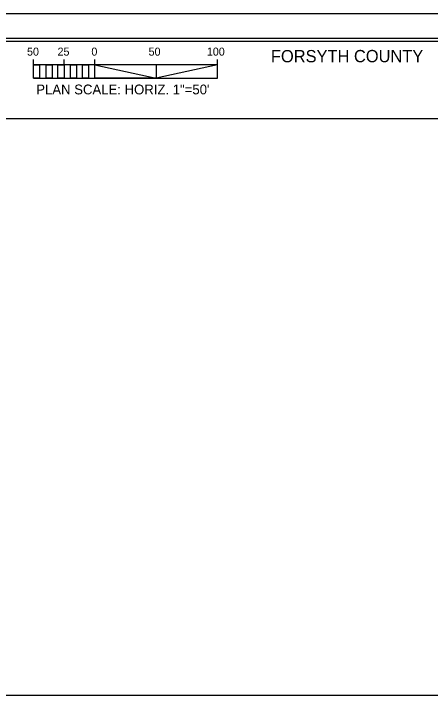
# Model space of a CAD drawing. Extents: x 0 to 7954, y -383 to 1504.
# Drawn here: x 1.851 to 2.416, y 0.894 to 1.833 of the extents above; entities that cross this region are included whole.
import ezdxf

# ---------------------------------------------------------------- set-up
doc = ezdxf.new("R2010")
doc.units = 0
for name, color, linetype in [('Scratch_Level_3', 7, 'Continuous'), ('UC Plan Profile Sheet 34 CELL', 7, 'Continuous'), ('UC Title Plan Sheet 34 CELL', 7, 'Continuous')]:
    doc.layers.add(name, color=color, linetype=linetype)

msp = doc.modelspace()

# ---------------------------------------------------------------- linework, layer by layer
at = {"layer": 'Scratch_Level_3'}
msp.add_lwpolyline([(0.36636, 0.9085), (0.36636, 1.69148), (2.46666, 1.69148), (2.46666, 1.49966), (2.75747, 1.49966), (2.75747, 0.9085)], close=True, dxfattribs=at)
at = {"layer": 'UC Plan Profile Sheet 34 CELL'}
for points in [[(0.02749, 0.00833), (2.83333, 0.00833), (2.83333, 1.83333), (0.02749, 1.83333)], [(0.04916, 0.04166), (2.82583, 0.04166), (2.82583, 1.8), (0.04916, 1.8)], [(2.80499, 1.79583), (0.30499, 1.79583), (0.30499, 0.04583), (2.80499, 0.04583)]]:
    msp.add_lwpolyline(points, close=True, dxfattribs=at)
at = {"layer": 'UC Title Plan Sheet 34 CELL'}
for p, q in [((1.87729, 1.74591), (1.87729, 1.77124)), ((1.91896, 1.76401), (1.91896, 1.77127)), ((1.96063, 1.76401), (1.96063, 1.77125)), ((2.12729, 1.76403), (2.12729, 1.77127)), ((2.12729, 1.764), (1.87729, 1.76401)), ((1.93587, 1.76402), (1.93587, 1.74591)), ((2.04396, 1.76403), (2.04396, 1.74592)), ((2.12729, 1.7459), (2.12729, 1.76403)), ((1.87729, 1.7459), (2.12729, 1.74591))]:
    msp.add_line(p, q, dxfattribs=at)
for points in [[(1.87729, 1.76401), (1.88554, 1.76401), (1.88554, 1.7459), (1.87729, 1.7459)], [(1.89461, 1.76402), (1.90286, 1.76401), (1.90286, 1.74589), (1.89463, 1.74589)], [(1.91071, 1.76401), (1.91896, 1.76401), (1.91896, 1.74592), (1.91071, 1.74592)], [(1.92762, 1.76401), (1.93587, 1.76402), (1.93587, 1.74591), (1.92762, 1.74591)], [(1.94412, 1.76402), (1.95237, 1.76403), (1.95237, 1.74589), (1.94412, 1.74591)], [(1.96063, 1.76401), (2.04396, 1.74592), (1.96063, 1.7459)], [(2.12729, 1.76403), (2.04396, 1.74592), (2.12729, 1.7459)]]:
    msp.add_lwpolyline(points, close=True, dxfattribs=at)

# ---------------------------------------------------------------- texts
at = {"layer": 'UC Plan Profile Sheet 34 CELL'}
msp.add_text('FORSYTH COUNTY', height=0.0166667, rotation=0.04517, dxfattribs=at).set_placement((2.19978, 1.76755))
at = {"layer": 'UC Title Plan Sheet 34 CELL'}
for s, height, p in [('50', 0.010867, (1.86873, 1.77661)), ('25', 0.010867, (1.91013, 1.77663)), ('0', 0.01087, (1.95609, 1.77662)), ('50', 0.010867, (2.03376, 1.77662)), ('100', 0.010867, (2.11282, 1.77664)), ('PLAN SCALE: HORIZ. 1"=50\'', 0.0133333, (1.88124, 1.72403))]:
    msp.add_text(s, height=height, rotation=0.00136, dxfattribs=at).set_placement(p)

doc.saveas('drawing.dxf')
